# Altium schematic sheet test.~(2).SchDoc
size A4
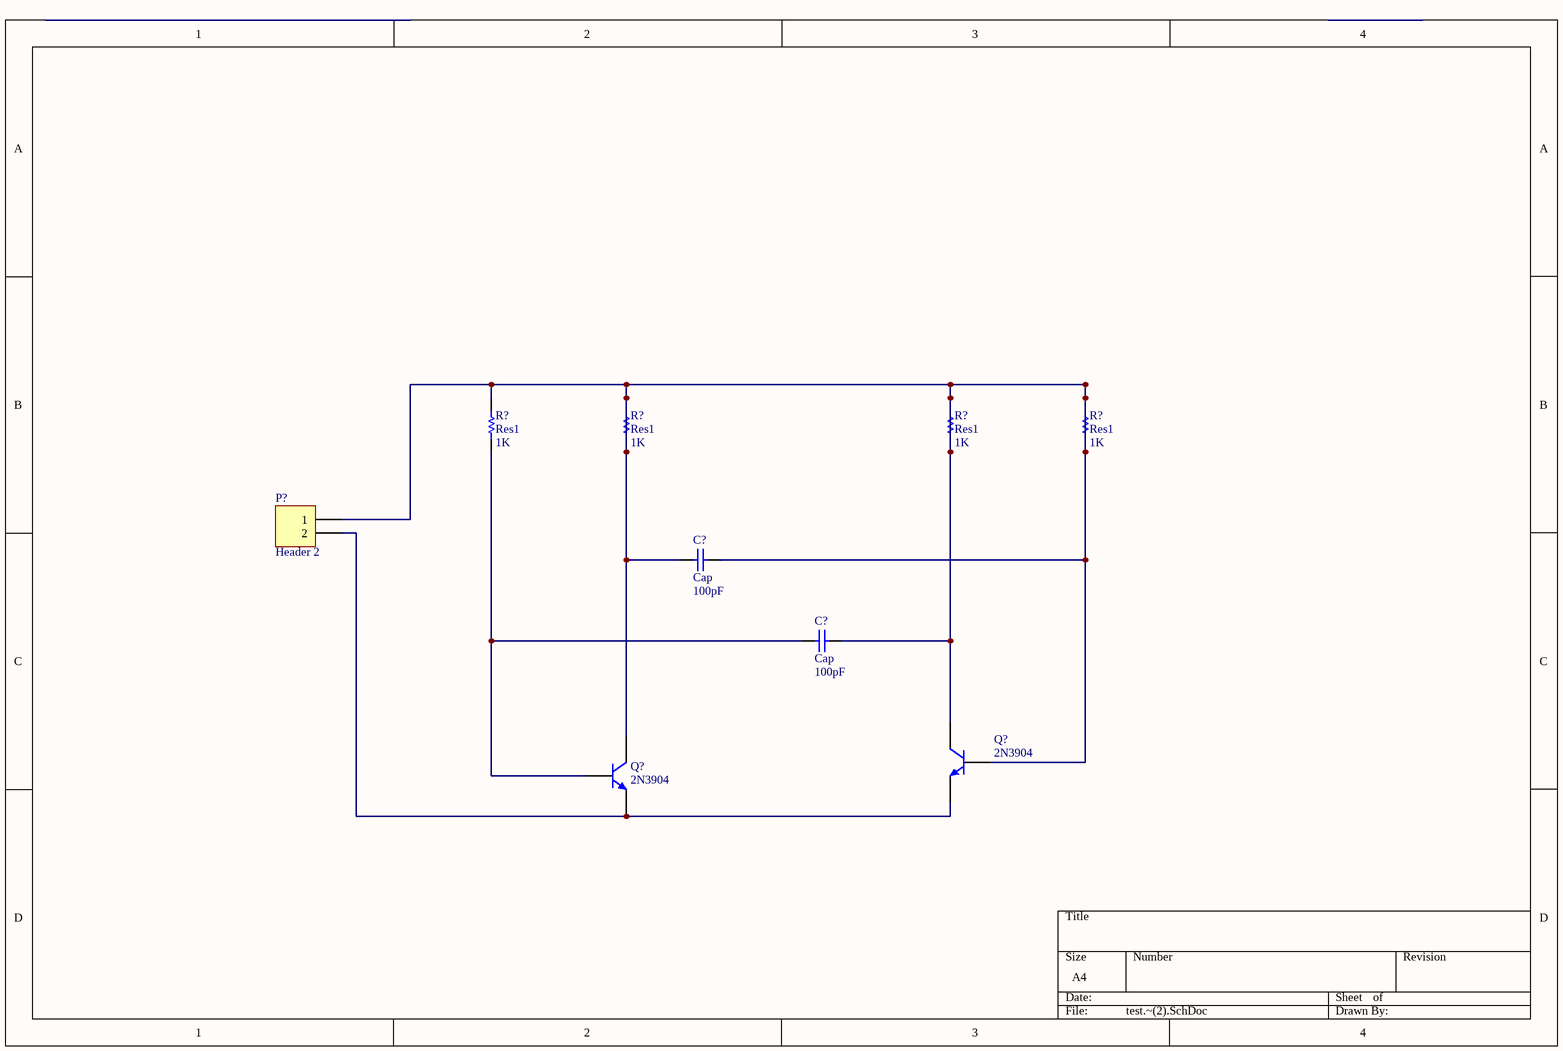
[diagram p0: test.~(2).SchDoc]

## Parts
(Parts that share a designator on the sheet are numbered #1, #2 ... from top to bottom, then left to right.)
C?#1  Cap  value 100pF  [RAD-0.3]
C?#2  Cap  value 100pF  [RAD-0.3]
P?  Header 2  [HDR1X2]
Q?#1  2N3904  [TO-92A]
Q?#2  2N3904  [TO-92A]
R?#1  Res1  value 1K  [AXIAL-0.3]
R?#2  Res1  value 1K  [AXIAL-0.3]
R?#3  Res1  value 1K  [AXIAL-0.3]
R?#4  Res1  value 1K  [AXIAL-0.3]

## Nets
NetC?#1_1: C?#1.1 C?#1.2 C?#2.2 P?.1 Q?#1.2(B) Q?#1.3(C) Q?#2.3(C) R?#1.1 R?#2.1 R?#2.2 R?#3.1 R?#3.2 R?#4.1 R?#4.2
NetC?#2_1: C?#2.1 Q?#2.2(B) R?#1.2
NetP?_2: P?.2 Q?#1.1(E) Q?#2.1(E)

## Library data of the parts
C?#1 C?#2 = Cap: Capacitor
P? = Header 2: Header, 2-Pin
Q?#1 Q?#2 = 2N3904: NPN General Purpose Amplifier
R?#1-R?#4 = Res1: Resistor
